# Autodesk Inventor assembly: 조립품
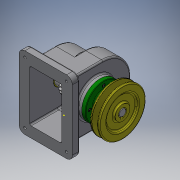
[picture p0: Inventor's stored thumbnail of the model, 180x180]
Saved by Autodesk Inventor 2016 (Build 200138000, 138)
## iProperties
Created: 2017-11
Part Number: 조립품
Material: 일반
Document SubType Name: Assembly
Designer: Administrator
Author: Administrator
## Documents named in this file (14)
- C:\Users\Administrator\Desktop\471107V1023\조립품.iam
- C:\Users\Administrator\Desktop\471107V1023\본체.ipt
- C:\Users\Administrator\Desktop\471107V1023\V-벨트풀리.ipt
- C:\Users\Administrator\Desktop\471107V1023\뒤커버.ipt
- C:\Users\Administrator\Desktop\471107V1023\멈춤나사 - M4 x 10.ipt
- 멈춤나사 - M4 x 10.ipt
- C:\Users\Administrator\Desktop\471107V1023\베어링 6002.ipt
- C:\Users\Administrator\Desktop\471107V1023\볼트 M3 x 8.ipt
- C:\Users\Administrator\Desktop\471107V1023\스퍼기어.ipt
- C:\Users\Administrator\Desktop\471107V1023\앞커버.ipt
- C:\Users\Administrator\Desktop\471107V1023\오일 실 15 30 7.ipt
- C:\Users\Administrator\Desktop\471107V1023\축.ipt
- C:\Users\Administrator\Desktop\471107V1023\키 - 5 x 5 x 18.ipt
- C:\Users\Administrator\Desktop\471107V1023\키 - 6 x 6 x 22.ipt
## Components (1 placed, 1 different names)
1. V-벨트풀리:1 — 각도:1
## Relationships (1: Angle 1)
- 각도:1 [Angle]: V-벨트풀리:1
